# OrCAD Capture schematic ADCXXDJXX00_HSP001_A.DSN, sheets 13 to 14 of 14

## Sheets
13 PAGE13 - POWER SUPPLIES: size B; title: ADC POWER SUPPLIES
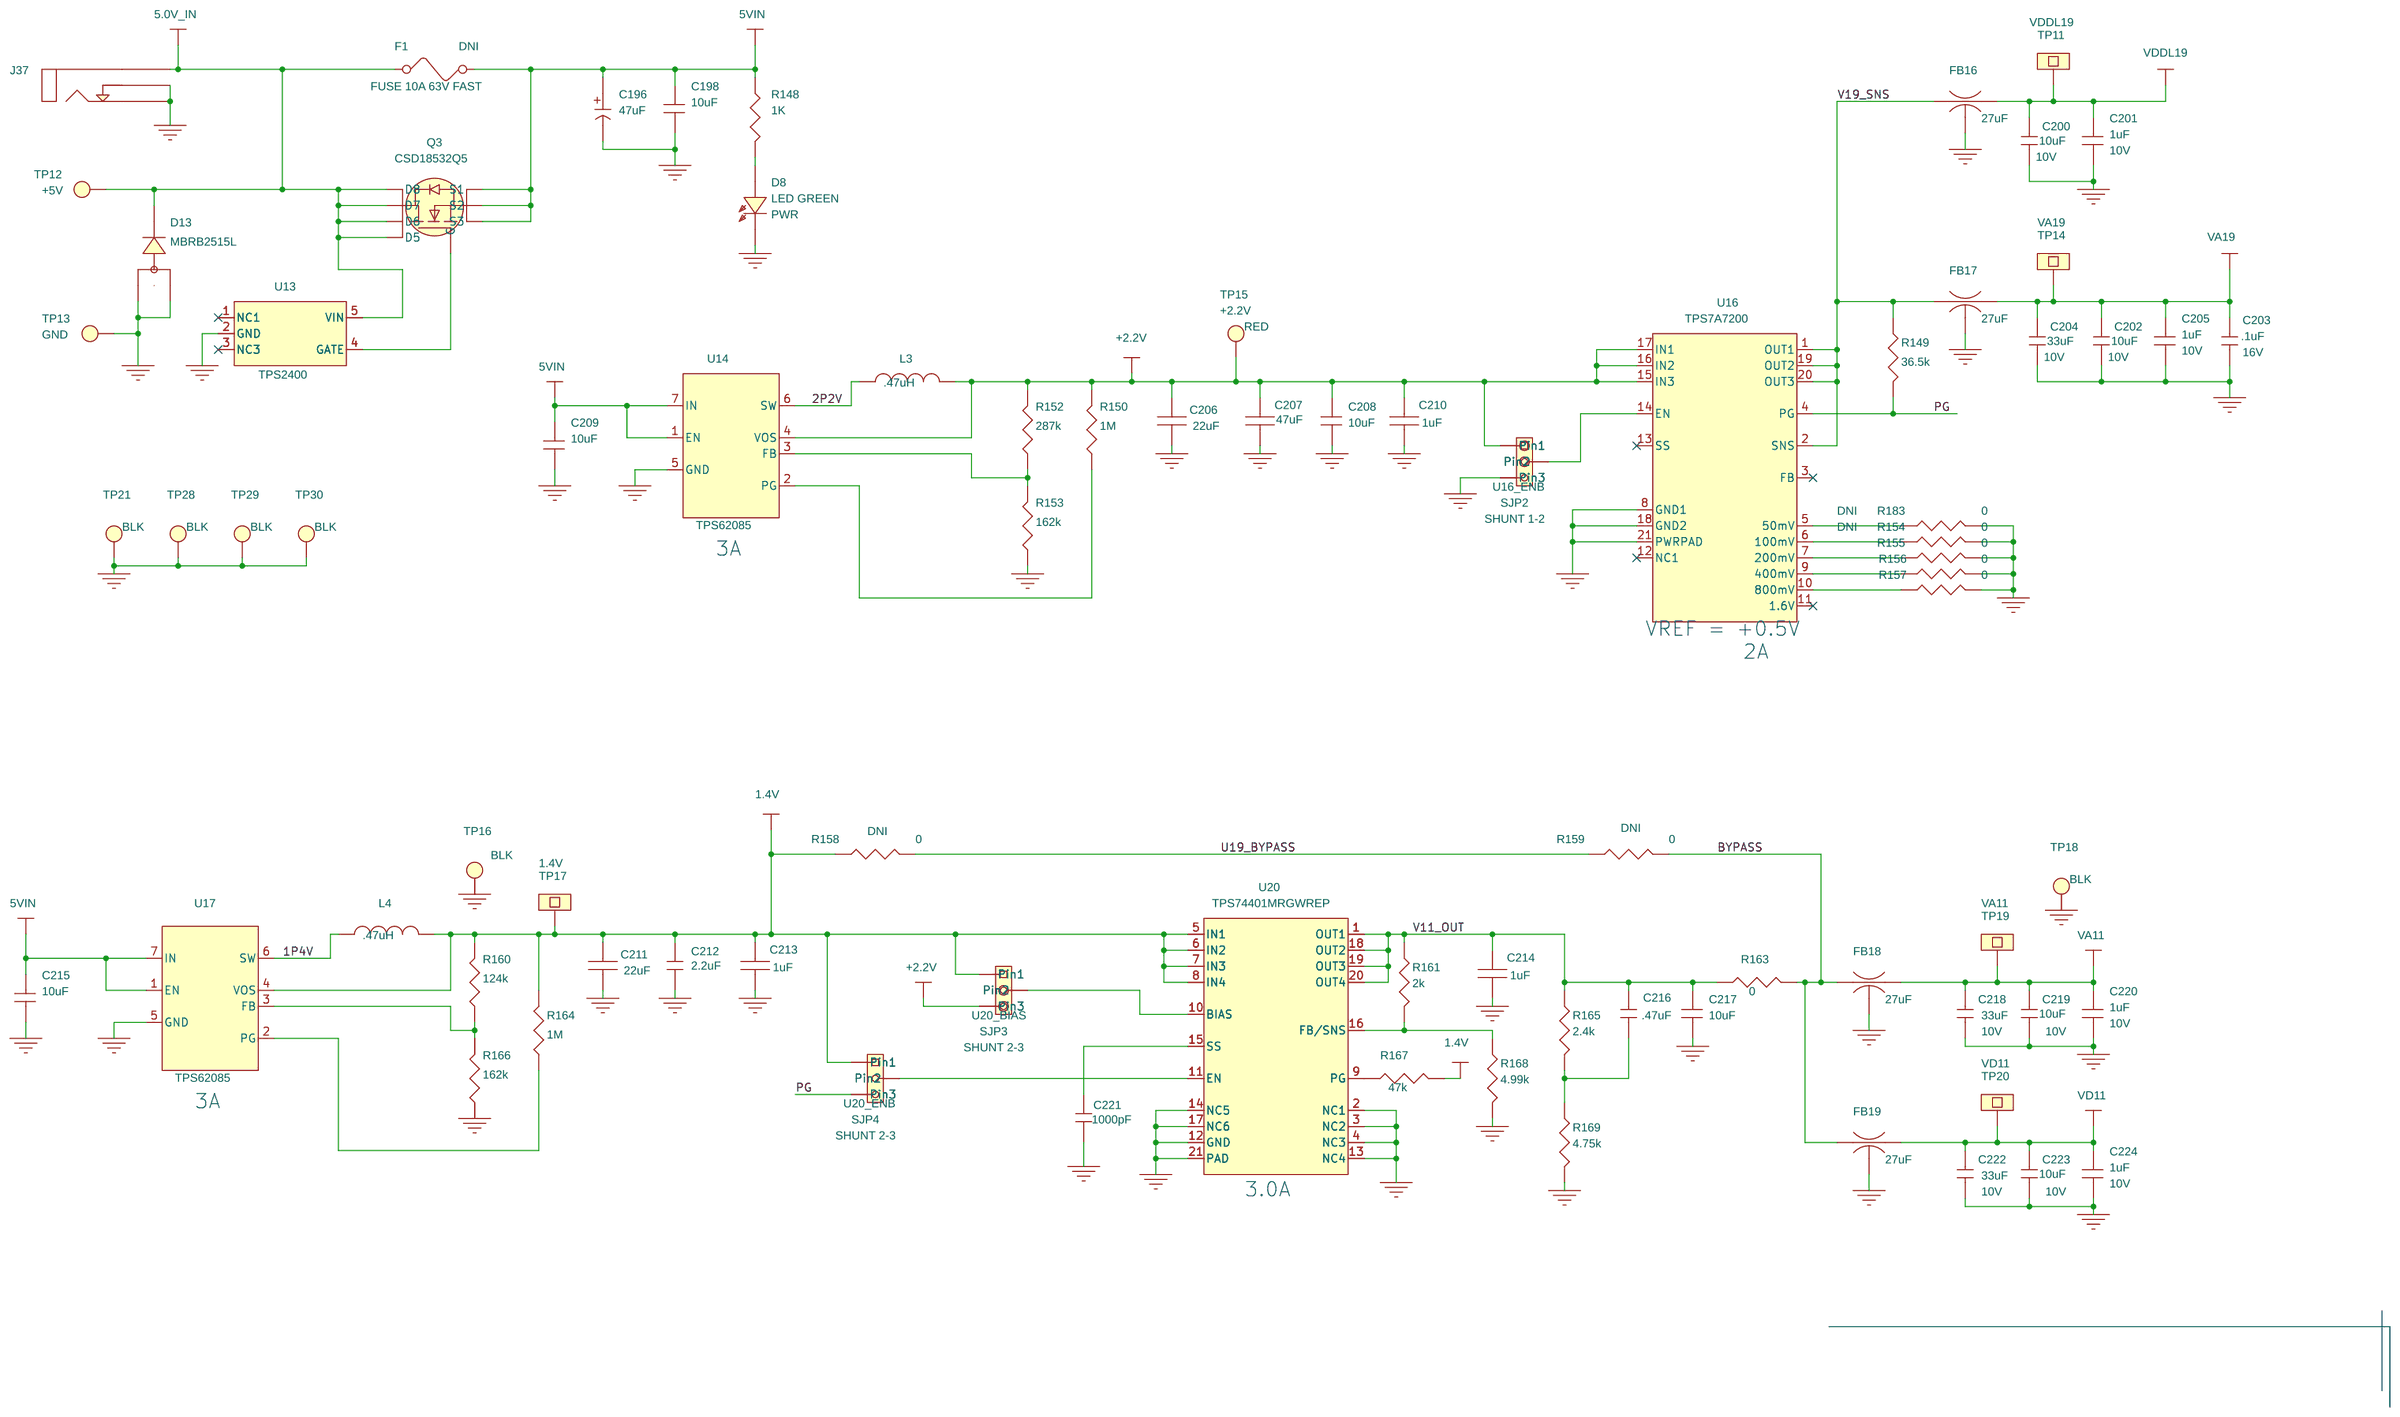
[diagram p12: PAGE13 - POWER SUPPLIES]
14 PAGE14 - POWER SUPPLIES: size B; title: POWER SUPPLIES
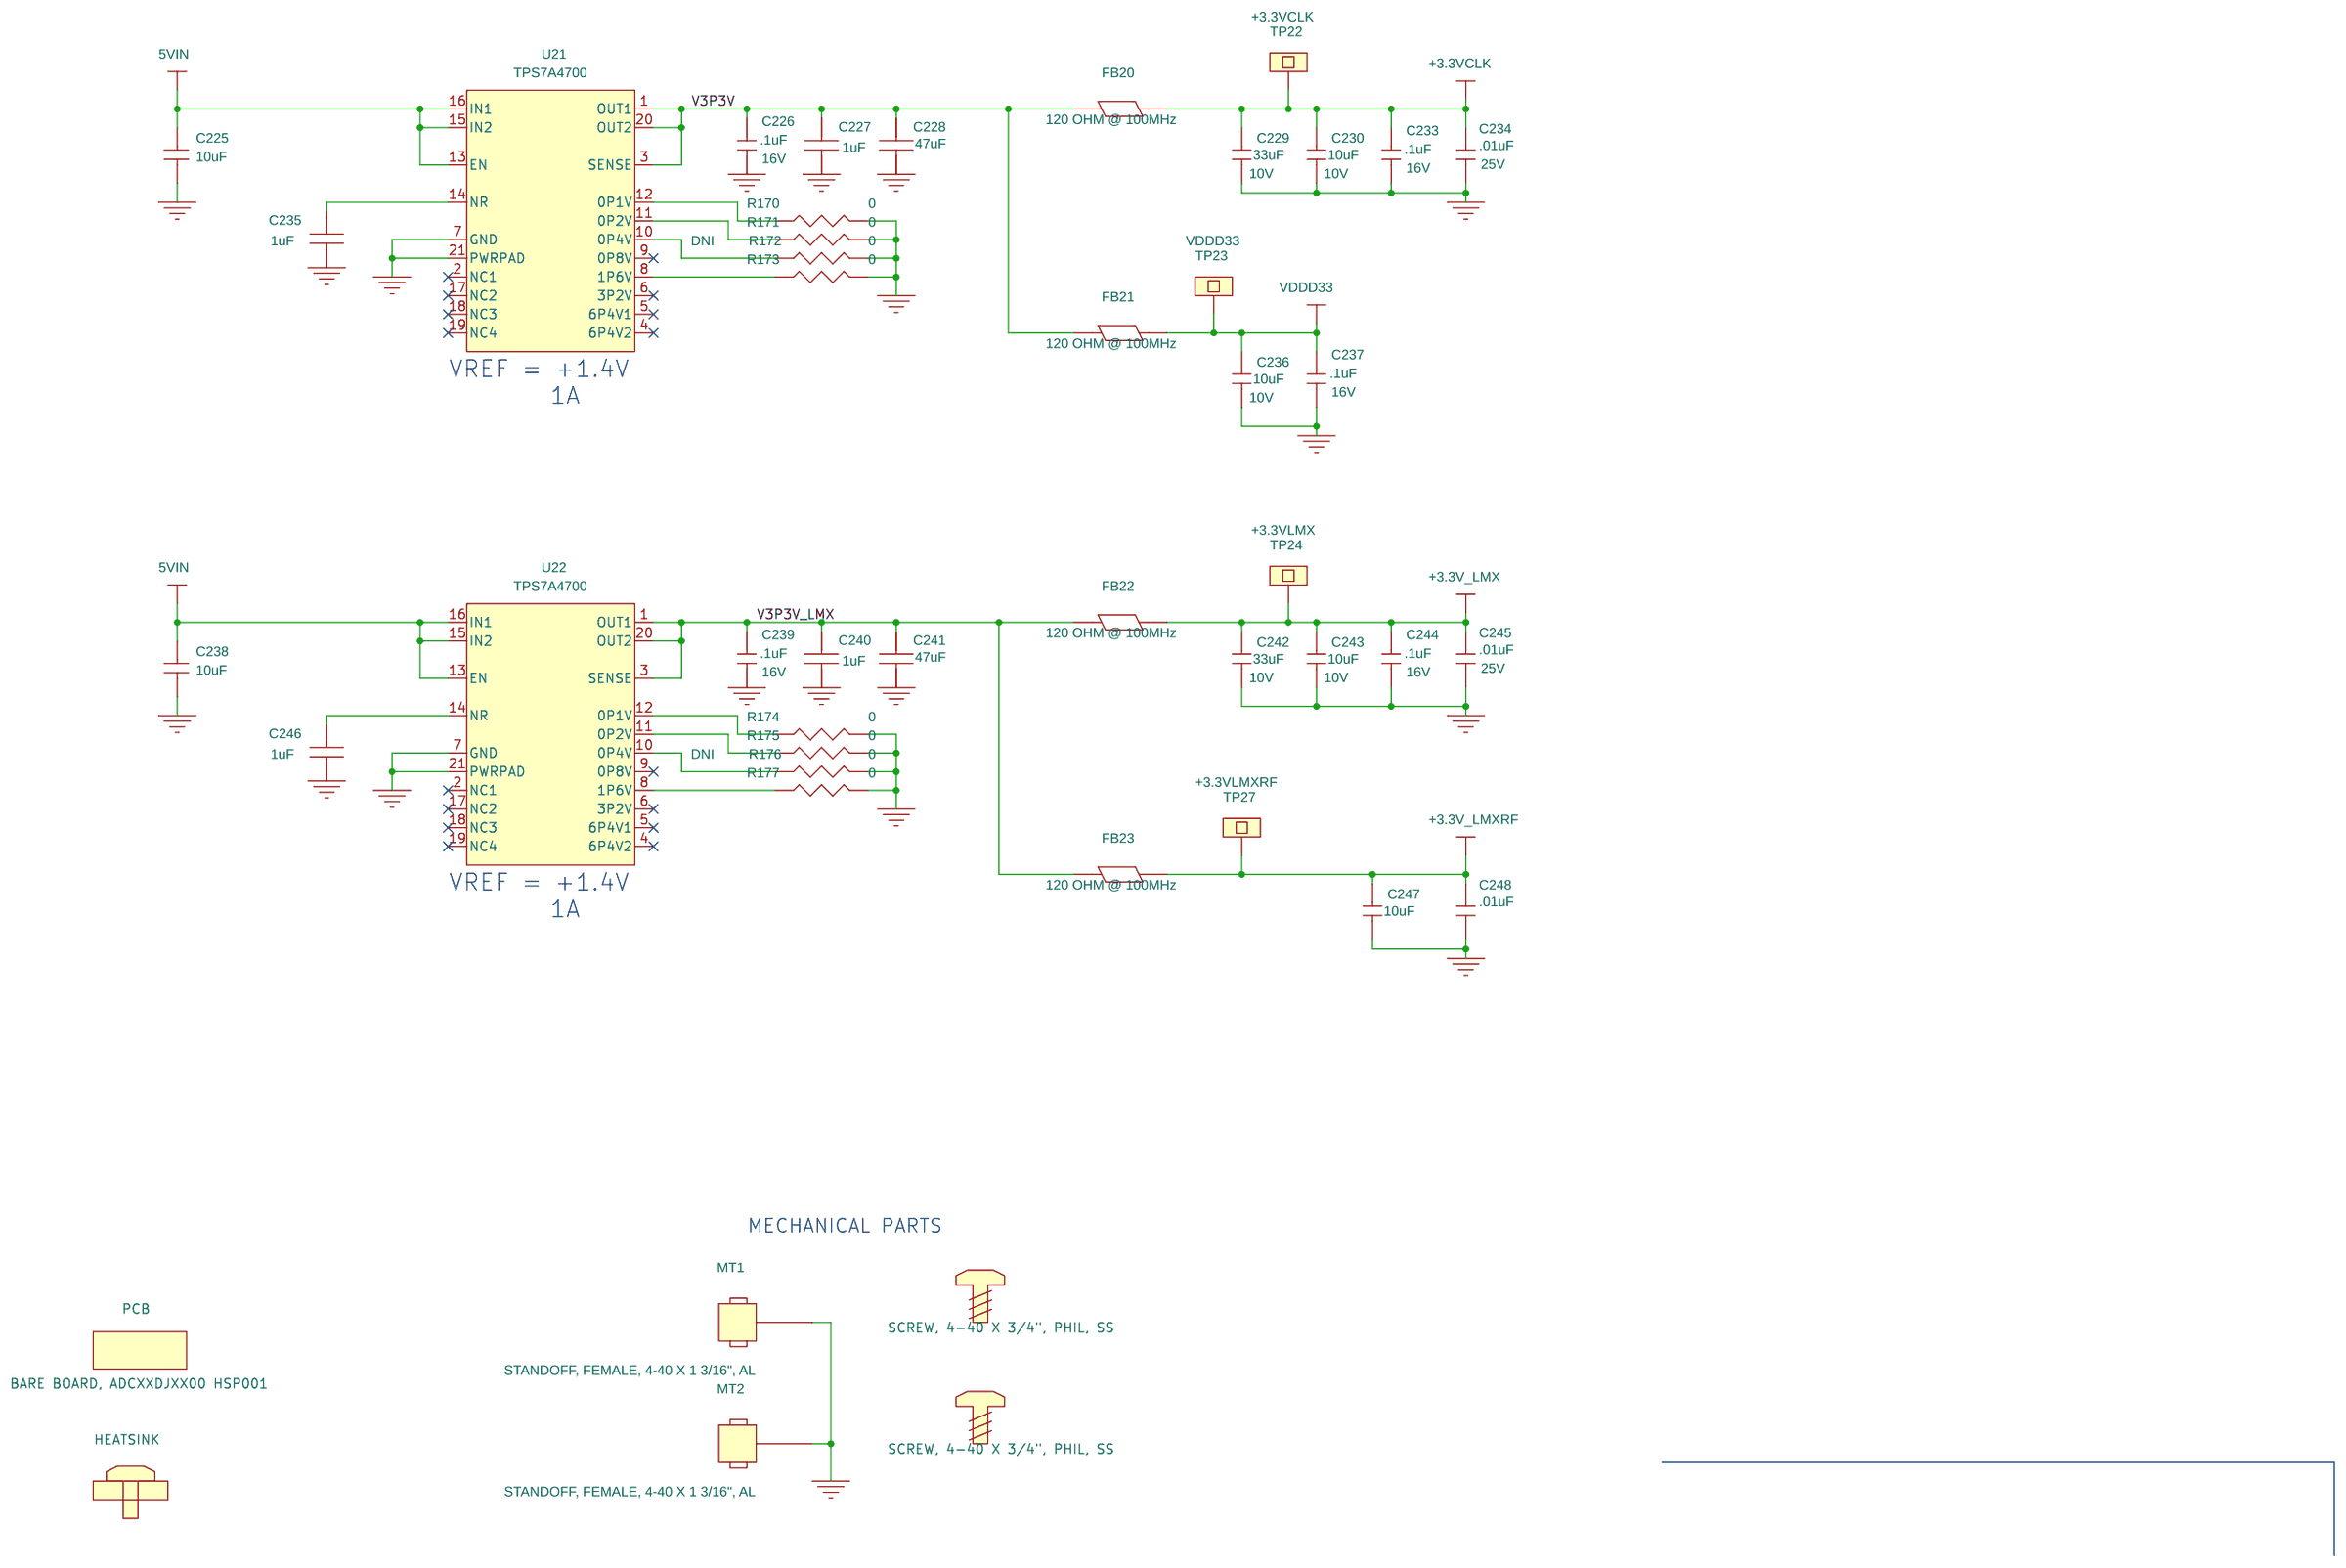
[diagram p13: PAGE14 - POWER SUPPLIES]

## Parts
sheet PAGE13 - POWER SUPPLIES
C196  47uF  [TANT_B]
C198  10uF  [0603]
C200  10uF  [0603]
C201  1uF  [0402]
C202  10uF  [0603]
C203  .1uF  [0402]
C204  33uF  [0805]
C205  1uF  [0402]
C206  22uF  [1206]
C207  47uF  [1206]
C208  10uF  [0603]
C209  10uF  [0805]
C210  1uF  [0402]
C211  22uF  [1206]
C212  2.2uF  [0603]
C213  1uF  [0402]
C214  1uF  [0402]
C215  10uF  [0805]
C216  .47uF  [0603]
C217  10uF  [0603]
C218  33uF  [0805]
C219  10uF  [0603]
C220  1uF  [0402]
C221  1000pF  [0603]
C222  33uF  [0805]
C223  10uF  [0603]
C224  1uF  [0402]
D8  LED GREEN  [LED_0805]
D13  MBRB2515L  [DIODE_MBRB2515L]
F1  FUSE 10A 63V FAST  [1206]
FB16  27uF  [1206_BEAD_NFM31P]
FB17  27uF  [1206_BEAD_NFM31P]
FB18  27uF  [1206_BEAD_NFM31P]
FB19  27uF  [1206_BEAD_NFM31P]
J37  CONN, JACK, PWR, MINI, R/A, TH  [CON_RAPC722_JACK_THVT_3]
L3  .47uH  [IND_SM_XFL4015]
L4  .47uH  [IND_SM_XFL4015]
Q3  CSD18532Q5  [SON_Q5B_8]
R148  1K  [0402]
R149  36.5k  [0402]
R150  1M  [0402]
R152  287k  [0402]
R153  162k  [0402]
R154  0  [0402]
R155  0  [0402]
R156  0  [0402]
R157  0  [0402]
R158  0  [0805]
R159  0  [0805]
R160  124k  [0402]
R161  2k  [0603]
R163  0  [0805]
R164  1M  [0402]
R165  2.4k  [0402]
R166  162k  [0402]
R167  47k  [0603]
R168  4.99k  [0603]
R169  4.75k  [0402]
R183  0  [0402]
RSHN1  SHUNT RES
RSHN2  SHUNT RES
RSHN3  SHUNT RES
SJP2  SOLDER JUMPER, 0402  [SMD_JUMPER_L_0402]
SJP3  SOLDER JUMPER, 0402  [SMD_JUMPER_L_0402]
SJP4  SOLDER JUMPER, 0402  [SMD_JUMPER_L_0402]
TP11  PROBE POINT  [PROBE_POINT_30PAD]
TP12  RED  [TP_THVT_125_RND_063D]
TP13  BLK  [TP_THVT_125_RND_063D]
TP14  PROBE POINT  [PROBE_POINT_30PAD]
TP15  RED  [TP_THVT_100_RND]
TP16  BLK  [TP_THVT_100_RND]
TP17  PROBE POINT  [PROBE_POINT_30PAD]
TP18  BLK  [TP_THVT_100_RND]
TP19  PROBE POINT  [PROBE_POINT_30PAD]
TP20  PROBE POINT  [PROBE_POINT_30PAD]
TP21  BLK  [TP_THVT_100_RND]
TP28  BLK  [TP_THVT_100_RND]
TP29  BLK  [TP_THVT_100_RND]
TP30  BLK  [TP_THVT_100_RND]
U13  TPS2400  [DBV5]
U14  TPS62085  [QFN_7_2MMx2MM]
U16  TPS7A7200  [QFN_20_199x199_0p65mm]
U17  TPS62085  [QFN_7_2MMx2MM]
U20  TPS74401MRGWREP  [QFN_20_197x197_0P65_RGW]
sheet PAGE14 - POWER SUPPLIES
C225  10uF  [0603]
C226  .1uF  [0402]
C227  1uF  [0402]
C228  47uF  [1206]
C229  33uF  [0805]
C230  10uF  [0603]
C233  .1uF  [0402]
C234  .01uF  [0201]
C235  1uF  [0402]
C236  10uF  [0603]
C237  .1uF  [0402]
C238  10uF  [0603]
C239  .1uF  [0402]
C240  1uF  [0402]
C241  47uF  [1206]
C242  33uF  [0805]
C243  10uF  [0603]
C244  .1uF  [0402]
C245  .01uF  [0201]
C246  1uF  [0402]
C247  10uF  [0603]
C248  .01uF  [0201]
FB20  120 OHM @ 100MHz  [1206]
FB21  120 OHM @ 100MHz  [1206]
FB22  120 OHM @ 100MHz  [1206]
FB23  120 OHM @ 100MHz  [1206]
MT1  STANDOFF, FEMALE, 4-40 X 1 3/16", AL  [MFG125_PLATED]
MT2  STANDOFF, FEMALE, 4-40 X 1 3/16", AL  [MFG125_PLATED]
PCB  BARE BOARD, ADCXXDJXX00 HSP001
R170  0  [0402]
R171  0  [0402]
R172  0  [0402]
R173  0  [0402]
R174  0  [0402]
R175  0  [0402]
R176  0  [0402]
R177  0  [0402]
TP22  PROBE POINT  [PROBE_POINT_30PAD]
TP23  PROBE POINT  [PROBE_POINT_30PAD]
TP24  PROBE POINT  [PROBE_POINT_30PAD]
TP27  PROBE POINT  [PROBE_POINT_30PAD]
U21  TPS7A4700  [QFN_20_199x199_0p65mm]
U22  TPS7A4700  [QFN_20_199x199_0p65mm]
Z_HEATSINK1  HEATSINK
Z_SCREW1  SCREW, 4-40 X 3/4", PHIL, SS
Z_SCREW2  SCREW, 4-40 X 3/4", PHIL, SS

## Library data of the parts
C196 = CAP_POL-B_0: Mfr_Name: AVX; Mfr_Part_Number: TPSB476K010R0250; TOL: 10%
C198 C208 C217 C225 C238 = CAP_NP_1: Mfr_Name: TDK; Mfr_Part_Number: C1608X5R1A106K080AC; TOL: 10%; VOLTAGE: 10V
C200 C202 C219 C223 = CAP0201_0: Mfr_Name: TDK; Mfr_Part_Number: C1608X5R1A106K080AC; TOL: 20%; VOLTAGE: 10V
C201 C205 C220 C224 = CAP_NP_1: Mfr_Name: TDK; Mfr_Part_Number: C1005X7S1A105K050BC; TOL: 10%; VOLTAGE: 10V
C203 C226 C233 C237 C239 C244 = CAP0603: Mfr_Name: MURATA; Mfr_Part_Number: GRM155R71C104KA88D; TOL: 10%; Voltage: 16V
C204 C218 C222 C229 C242 = CAP0201_0: Mfr_Name: TDK; Mfr_Part_Number: C2012X5R1A336M125AC; TOL: 20%; VOLTAGE: 10V
C206 C211 = CAP: Mfr_Name: MURATA; Mfr_Part_Number: GRM31CR71A226KE15L; TOL: 10%; VOLTAGE: 10V
C207 C228 C241 = CAP_NP_0: Mfr_Name: MURATA; Mfr_Part_Number: GRM31CR61A476ME15L; TOL: 20%; VOLTAGE: 10V
C209 C215 = CAP_NP_1: Mfr_Name: MURATA; Mfr_Part_Number: GRM21BR61E106KA73L; TOL: 10%; VOLTAGE: 25V
C210 C213 C214 C227 C235 C240 C246 = CAP_NP_0: Mfr_Name: TDK; Mfr_Part_Number: C1005X7S1A105K050BC; TOL: 10%; VOLTAGE: 10V
C212 = CAP_0603_2.2uF
C216 = CAP_0603_.47uF: Mfr_Part_Number: 0603YD474KAT2A
C221 = CAP_0603_1000pF
D8 = LED_GREEN_0: Mfr_Part_Number: LTST-C170KGKT; TI_SILKTEXT: PWR
D13 = DIODE_MBRB2515L
F1 = FUSE_0: Mfr_Name: TE Connectivity; Mfr_Part_Number: 1206SFF200F/63-2_DNI; Note: DNI
FB16-FB19 = BEAD_NFM31P: Mfr_Name: Murata; Mfr_Part_Number: NFM31PC276B0J3; Tolerance: 20%
J37 = CONN_JACK_PWR: Mfr_Name: SWITCHCRAFT; Mfr_Part_Number: RAPC722X
L3 L4 = CHOKE: Mfr_Name: Coilcraft; Mfr_Part_Number: XFL4015-471MEB
Q3 = CSD18532Q5B: Mfr_Name: Texas Instruments
R148 = Res_0402_1k: TOL: 1%
R149 = Res_0402_Zero_H: Mfr_Name: PANASONIC; Mfr_Part_Number: ERJ-2RKF3652X
R150 = R: Mfr_Name: PANASONIC; Mfr_Part_Number: ERJ-2RKF1004X; TOL: 1%
R152 = Res_0603_Zero_H: Mfr_Part_Number: ERJ-2RKF2873X
R153 = R: Mfr_Name: PANASONIC; Mfr_Part_Number: ERJ-2RKF1623X; TOL: 1%
R154 R183 = R: Mfr_Name: PANASONIC; Mfr_Part_Number: ERJ-2GE0R00X_DNI; Note: DNI; TOL: 5%
R155-R157 = R: Mfr_Name: PANASONIC; Mfr_Part_Number: ERJ-2GE0R00X; TOL: 5%
R158 R159 = Res_0402_Zero_H_DNI: Mfr_Part_Number: ERJ-6GEY0R00V_DNI; Note: DNI
R160 = Res_0603_Zero_H: Mfr_Part_Number: ERJ-2RKF1243X
R161 = Res_0603_1.87K: Mfr_Part_Number: ERJ-3EKF2001V
R163 = Res_0402_Zero_H_DNI: Mfr_Part_Number: ERJ-6GEY0R00V
R164 = R: Mfr_Name: Panasonic; Mfr_Part_Number: ERJ-2RKF1004X; TOL: 1%
R165 = Res_0603_12.4k: Mfr_Part_Number: ERJ-2RKF2401X
R166 = R: Mfr_Name: PANASONIC; Mfr_Part_Number: ERJ-2RKF1623X
R167 = Res_0603_47K
R168 = Res_0603_4.99K
R169 = Res_0603_10k: Mfr_Part_Number: ERJ-2RKF4751X
RSHN1-RSHN3 = SHUNT_RES: Mfr_Name: PANASONIC
SJP2 = SMD_JUMPER_1x3: Mfr_Name: DNI; Mfr_Part_Number: DNI; Note: SHUNT 1-2; TI_SILK: SHUNT 1-2; TI_Silktext: U16_ENB
SJP3 = SMD_JUMPER_1x3: Mfr_Name: DNI; Mfr_Part_Number: DNI; Note: SHUNT 2-3; TI_SILK: SHUNT 1-2; TI_Silktext: U20_BIAS
SJP4 = SMD_JUMPER_1x3: Mfr_Name: DNI; Mfr_Part_Number: DNI; Note: SHUNT 2-3; TI_SILK: SHUNT 1-2; TI_Silktext: U20_ENB
TP11 = PROBE_POINT_0: TI_Silktext: VDDL19
TP12 = TESTLOOP_BLACK: Mfr_Name: KEYSTONE; Mfr_Part_Number: 5010; TI_SILKTEXT: +5V
TP13 = TESTLOOP_BLACK: Mfr_Name: KEYSTONE; Mfr_Part_Number: 5011; TI_SILKTEXT: GND
TP14 = PROBE_POINT_0: TI_Silktext: VA19
TP15 = TESTLOOP_RED: Mfr_Name: KEYSTONE; Mfr_Part_Number: 5000; TI_SILKTEXT: +2.2V
TP16 TP18 TP21 TP28-TP30 = TESTPOINT_BLK: Mfr_Name: KEYSTONE; Mfr_Part_Number: 5001
TP17 = PROBE_POINT_0: TI_Silktext: 1.4V
TP19 = PROBE_POINT_0: TI_Silktext: VA11
TP20 = PROBE_POINT_0: TI_Silktext: VD11
U13 = TPS2400: Mfr_Name: Texas Instruments; Mfr_Part_Number: TPS2400DBVT
U14 U17 = TPS62085_62086_62087: Mfr_Name: Texas Instruments; Mfr_Part_Number: TPS62085RLTR
U16 = TPS7A7300
U20 = TPS74401: Mfr_Name: Texas Instruments
C230 C236 C243 C247 = CAP0201_0: Mfr_Name: TDK; Mfr_Part_Number: C1608X5R1A106K080AC; TOL: 10%; VOLTAGE: 10V
C234 C245 C248 = CAP0402_0: Mfr_Name: MURATA; Mfr_Part_Number: GRM155R71E103KA01D; TOL: 10V; Voltage: 25V
FB20-FB23 = FERRITE_BEAD_0402_H: Isat: 500mA; Mfr_Name: MURATA; Mfr_Part_Number: BLM31PG121SN1L
MT1 MT2 = MOUNTING_HOLE: Mfr_Name: RAF; Mfr_Part_Number: 1648-440-AL
PCB = BARE_BOARD: Mfr_Name: TTM; Mfr_Part_Number: ADCXXDJXX00 HSP001 REV A
R170 R171 R173-R175 R177 = R: Mfr_Name: PANASONIC; Mfr_Part_Number: ERJ-2GE0R00X
R172 R176 = R: Mfr_Name: PANASONIC; Mfr_Part_Number: ERJ-2GE0R00X_DNI; Note: DNI
TP22 = PROBE_POINT_0: TI_Silktext: +3.3VCLK
TP23 = PROBE_POINT_0: TI_Silktext: VDDD33
TP24 = PROBE_POINT_0: TI_Silktext: +3.3VLMX
TP27 = PROBE_POINT_0: TI_Silktext: +3.3VLMXRF
U21 U22 = TPS7A4700: Mfr_Name: Texas Instruments; Mfr_Part_Number: TPS7A4700RGWT
Z_HEATSINK1 = HEATSINK: Mfr_Name: AAVID; Mfr_Part_Number: 375324B00035G
Z_SCREW1 Z_SCREW2 = STANDOFF-SCREW: Mfr_Part_Number: PMSSS 440 0075 PH; Note: SCREW FOR STANDOFF

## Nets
1.4V: C211.1 C212.1 C213.1 L4.2 R158.2 R160.1 R164.1 R167.2 SJP3.1(Pin1) SJP4.1(Pin1) TP17.1 U17.4(VOS) U20.5(IN1) U20.6(IN2) U20.7(IN3) U20.8(IN4)
5.0V_IN: D13.4 F1.1 J37.1 Q3.5(D5) Q3.6(D6) Q3.7(D7) Q3.8(D8) TP12.1(TP) U13.5(VIN)
5VIN: C196.1 C198.1 C209.1 C215.1 C225.1 C238.1 F1.2 Q3.1(S1) Q3.2(S2) Q3.3(S3) R148.1 U14.1(EN) U14.7(IN) U17.1(EN) U17.7(IN) U21.13(EN) U21.15(IN2) U21.16(IN1) U22.13(EN) U22.15(IN2) U22.16(IN1)
+2.2V: C206.1 C207.1 C208.1 C210.1 L3.2 R150.1 R152.1 SJP2.1(Pin1) SJP3.3(Pin3) TP15.1(TP) U14.4(VOS) U16.15(IN3) U16.16(IN2) U16.17(IN1)
+3.3V_LMX: C242.1 C243.1 C244.1 C245.1 FB22.2 TP24.1 ; also on sheet 5
+3.3V_LMXRF: C247.1 C248.1 FB23.2 TP27.1 ; also on sheet 5
+3.3VCLK: C229.1 C230.1 C233.1 C234.1 FB20.2 TP22.1 ; also on sheet 6 7
GND: C196.2 C198.2 C200.2 C201.2 C202.2 C203.2 C204.2 C205.2 C206.2 C207.2 C208.2 C209.2 C210.2 C211.2 C212.2 C213.2 C214.2 C215.2 C217.2 C218.2 C219.2 C220.2 C221.2 C222.2 C223.2 C224.2 C225.2 C226.2 C227.2 C228.2 C229.2 C230.2 C233.2 C234.2 C235.2 C236.2 C237.2 C238.2 C239.2 C240.2 C241.2 C242.2 C243.2 C244.2 C245.2 C246.2 C247.2 C248.2 D8.2(CATHODE) D13.1 D13.3 FB16.2 FB17.2 FB18.2 FB19.2 J37.2 J37.3 MT1.1 MT2.1 R153.2 R154.1 R155.1 R156.1 R157.1 R166.2 R168.2 R169.2 R170.1 R171.1 R172.1 R173.1 R174.1 R175.1 R176.1 R177.1 R183.1 SJP2.3(Pin3) TP13.1(TP) TP16.1(TP) TP18.1(TP) TP21.1(TP) TP28.1(TP) TP29.1(TP) TP30.1(TP) U13.2(GND) U14.5(GND) U16.8(GND1) U16.18(GND2) U16.21(PWRPAD) U17.5(GND) U20.2(NC1) U20.3(NC2) U20.4(NC3) U20.12(GND) U20.13(NC4) U20.14(NC5) U20.17(NC6) U20.21(PAD) U21.7(GND) U21.21(PWRPAD) U22.7(GND) U22.21(PWRPAD) ; also on sheet 2 3 4 5 6 7 8 9 10 11 12
V3P3V: C226.1 C227.1 C228.1 FB20.1 FB21.1 U21.1(OUT1) U21.3(SENSE) U21.20(OUT2)
V3P3V_LMX: C239.1 C240.1 C241.1 FB22.1 FB23.1 U22.1(OUT1) U22.3(SENSE) U22.20(OUT2)
V11_OUT: C214.1 C216.1 C217.1 R161.1 R163.2 R165.1 U20.1(OUT1) U20.18(OUT2) U20.19(OUT3) U20.20(OUT4)
V19_SNS: FB16.1 FB17.1 R149.1 U16.1(OUT1) U16.2(SNS) U16.19(OUT2) U16.20(OUT3)
VDDD33: C236.1 C237.1 FB21.2 TP23.1 ; also on sheet 3 11 12
VDDL19: C200.1 C201.1 FB16.3 TP11.1 ; also on sheet 12
1P4V: L4.1 U17.6(SW)
2: D13.2
2P2V: L3.1 U14.6(SW)
BYPASS: FB18.1 FB19.1 R159.1 R163.1
PG: R149.2 SJP4.3(Pin3) U16.4(PG)
U19_BYPASS: R158.1 R159.2
VA11: C218.1 C219.1 C220.1 FB18.3 TP19.1 ; also on sheet 4
VA19: C202.1 C203.1 C204.1 C205.1 FB17.3 TP14.1 ; also on sheet 2 3 4
VD11: C222.1 C223.1 C224.1 FB19.3 TP20.1 ; also on sheet 4
N18340257: D8.1(ANODE) R148.2
N19631466: C235.1 U21.14(NR)
N19631491: R173.2 U21.8(1P6V)
N19631493: R171.2 U21.11(0P2V)
N19631495: R170.2 U21.12(0P1V)
N19631505: R172.2 U21.10(0P4V)
N19955835: Q3.4(G) U13.4(GATE)
N20042801: R155.2 U16.7(200mV)
N20043120: R154.2 U16.6(100mV)
N20043460: R156.2 U16.9(400mV)
N20043630: R157.2 U16.10(800mV)
N20101312: R152.2 R153.1 U14.3(FB)
N20101373: R150.2 U14.2(PG)
N20111831: R160.2 R166.1 U17.3(FB)
N20111884: R164.2 U17.2(PG)
N20113519: C216.2 R165.2 R169.1
N20150497: SJP2.2(Pin2) U16.14(EN)
N20151052: SJP3.2(Pin2) U20.10(BIAS)
N20220969: C246.1 U22.14(NR)
N20220990: R177.2 U22.8(1P6V)
N20220992: R175.2 U22.11(0P2V)
N20220994: R174.2 U22.12(0P1V)
N20221006: R176.2 U22.10(0P4V)
N20382261: C221.1 U20.15(SS)
N20399374: R161.2 R168.1 U20.16(FB/SNS)
N20400206: SJP4.2(Pin2) U20.11(EN)
N20599204: R183.2 U16.5(50mV)
N20745185: R167.1 U20.9(PG)

Not connected (* = marked no-connect by the designer): U13 1(NC1)* 3(NC3)*; U16 3(FB)* 11(1.6V)* 12(NC1)* 13(SS)*; U21 2(NC1)* 4(6P4V2)* 5(6P4V1)* 6(3P2V)* 9(0P8V)* 17(NC2)* 18(NC3)* 19(NC4)*; U22 2(NC1)* 4(6P4V2)* 5(6P4V1)* 6(3P2V)* 9(0P8V)* 17(NC2)* 18(NC3)* 19(NC4)*

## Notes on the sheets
sheet 13
- 3A
- VREF = +0.5V
           2A
- 3A
- 3.0A
sheet 14
- VREF = +1.4V
          1A
- VREF = +1.4V
          1A
- MECHANICAL PARTS
